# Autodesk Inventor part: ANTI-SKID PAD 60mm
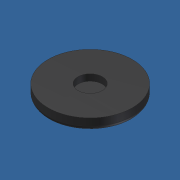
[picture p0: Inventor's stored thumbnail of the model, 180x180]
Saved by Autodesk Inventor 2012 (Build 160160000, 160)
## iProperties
Created: 2007-03
Part Number: ANTI-SKID PAD 60mm
Material: Rubber
Document SubType Name: Modeling
Designer: Andy Moles
Density: 0.93 g/cm^3
Mass: 12.9686 g
Surface Area: 54.014 cm^2
Volume: 13.9448 cm^3
Author: Andy Moles
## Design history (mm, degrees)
sketch "Sketch1"
  geometry: C1 r 26 at (0, 0); 1 further point
  constraints: 1 centre point, 1 coincident
  dimensions: "d0" = 52 diameter of C1
extrude "Extrusion1" new body sketch "Sketch1" distance "d1" = 7; taper "d2" = 0 deg
sketch "Sketch2"
  geometry: C1 r 26 at (0, 0) reference; C2 r 7.5 at (0, 0)
  constraints: 1 centre point, 1 coincident
  dimensions: "d3" = 15 diameter of C2
extrude "Extrusion2" cut sketch "Sketch2" distance "d4" = 4; taper "d5" = 0 deg
fillet "Fillet1" dims "d6" = 2.5
body "Solid1"
